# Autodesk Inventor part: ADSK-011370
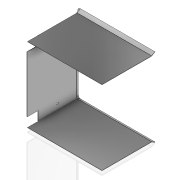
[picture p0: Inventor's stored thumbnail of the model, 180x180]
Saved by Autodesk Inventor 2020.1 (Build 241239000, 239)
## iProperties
Created: 1999-12
Part Number: ADSK-011370
Material: Acier inoxydable austénitique
Document SubType Name: Modeling
Designer: glanglot
Density: 8.03 g/cm^3
Appearance: Chrom - poliert
Mass: 2406.63 g
Surface Area: 4035.99 cm^2
Volume: 299.705 cm^3
Control State: 0
Checked Out: False
Master: False
Shininess: 0.0
Length Units: 11269
Angle Units: 11279
Time Units: 11290
Mass Units: 11283
Length Display Precision: 3
Angle Display Precision: 2
Compacted: True
Dimensions: 317,5x323,8x218,6 mm
Mass: 2,407 kg
Density: 0.0
Volumn: 0.0
Area: 0.0
PropertySet Name: Model Information
Author: glanglot
Revision Number: -
Title: ADSK-011370
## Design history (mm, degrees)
node "Extrusion1" dims "d5" = 204, "d6" = 0
  sketch "Sketch1"
    geometry: L1 (309.5, 154)-(0, 154); L2 (0, 154)-(0, -154); L3 (0, -154)-(309.5, -154); L4 (309.5, -154)-(309.5, -152.5); L5 (309.5, -152.5)-(1.5, -152.5); L6 (1.5, -152.5)-(1.5, 152.5); L7 (1.5, 152.5)-(309.5, 152.5); L8 (309.5, 152.5)-(309.5, 154); 2 further points
    constraints: 16 end point, 6 parallel, 2 equal length, 1 coincident, 1 horizontal, 1 midpoint, 1 perpendicular
    dimensions: "d1" = 1.5 distance of L7.end L1.start; "d2" = 308 distance of L6.end L7.end (= d44); "d3" = 1.5 distance between parallel lines of L2 L6 (= d1); "d44" = 308 distance between parallel lines of L1 L3
node "Fillet1" dims "d8" = 1.5 (= d1)
node "Fillet2" dims "d9" = 3 (= 2 x d1)
workplane "Work Plane1"
workplane "Work Plane2"
workplane "Work Plane3"
workplane "Work Plane4"
workplane "Work Plane5"
node "Extrusion2" dims "d16" = 228.6, "d17" = 0
  sketch "Sketch2"
    geometry: L1 (-1.5, 0)-(0, 0) reference; L2 (0, 0)-(8, -13.856); L3 (8, -13.856)-(6.701, -14.606); L4 (6.701, -14.606)-(-1.5, -0.402); L5 (-1.5, 0)-(-1.5, -0.402)
    constraints: 8 end point, 2 perpendicular, 1 parallel
    dimensions: "d13" = 16 distance of L1.end L2.end; "d14" = 1.5 distance of L2.end L3.end (= d1); "d15" = 120 deg angle of L1 L2
node "Extrusion3" dims "d21" = 228.6, "d22" = 0
  sketch "Sketch3"
    geometry: L1 (-306.5, 0)-(-309.5, 0) reference; L2 (-309.5, 0)-(-317.5, -13.856); L3 (-317.5, -13.856)-(-316.201, -14.606); L4 (-316.201, -14.606)-(-308, -0.402); L5 (-308, 0)-(-308, -0.402)
    constraints: 8 end point, 2 perpendicular, 1 midpoint, 1 parallel
    dimensions: "d18" = 16 distance of L1.end L2.end (= d13); "d19" = 1.5 distance of L2.end L3.end (= d1); "d20" = 120 deg angle of L1 L2 (= d15)
workaxis "Work Axis1"
node "Revolution1" dims "d23" = 90 deg
node "Extrusion4" dims "d32" = 3 (= 2 x d1), "d33" = 0
  sketch "Sketch5"
    geometry: L1 (0, 0)-(0, 302) reference; L2 (0, 305)-(-204, 305) reference; L3 (0, 305)-(0, 302) reference; L4 (-204, 302)-(-204, 305) reference; L5 (-45, 305)-(-45, 267); L6 (-45, 267)-(0, 267)
    constraints: 4 end point, 2 point on line, 1 parallel, 1 perpendicular
    dimensions: "d30" = 38 distance between parallel lines of L2 L6; "d31" = 45 distance between parallel lines of L1 L5
node "Hole1" dims "d38" = 8, "d39" = 9.525, "d40" = 6.35, "d41" = 60 deg, "d42" = 19.05, "d43" = 118 deg, "d45" = 6
  sketch "Sketch6"
    geometry: L1 (80, 280)-(80, 22); L2 (204, -3)-(204, 305); 3 further points
    constraints: 4 end point, 2 midpoint, 2 vertical, 1 coincident, 1 horizontal alignment
    dimensions: "d46" = 258 distance of L1.start L1.end; "d47" = 124 distance between parallel lines of L1 L2
node "Mirror1"
node "Fillet3" dims "d24" = 1.5 (= d1)
node "Fillet4" dims "d25" = 3 (= 2 x d1)
workplane "Work Plane6"
workplane "Work Plane7"
workplane "Work Plane9"
node "Solide1"
node "Corps solides"
node "Corps surfaciques"
sketch "Sketch4"
  geometry: L1 (-0.402, 0)-(-14.606, 8.201) reference; L2 (0, 0)-(-0.402, 0) reference; L3 (0, 1.5)-(0, 0) reference; L4 (-13.856, 9.5)-(0, 1.5) reference; L5 (-14.606, 8.201)-(-13.856, 9.5) reference; L6 (-58.328, -1.5)-(247.721, -1.5) reference
other parameters: "d0" = 304.8, "d7" = 152.4 (= 0.5 x d0), "d10" = 1.5 (= d8), "d11" = 1.5 (= d8), "d12" = 1.5 (= d8), "d26" = -114.3, "d27" = 114.3, "d34" = 228.6
